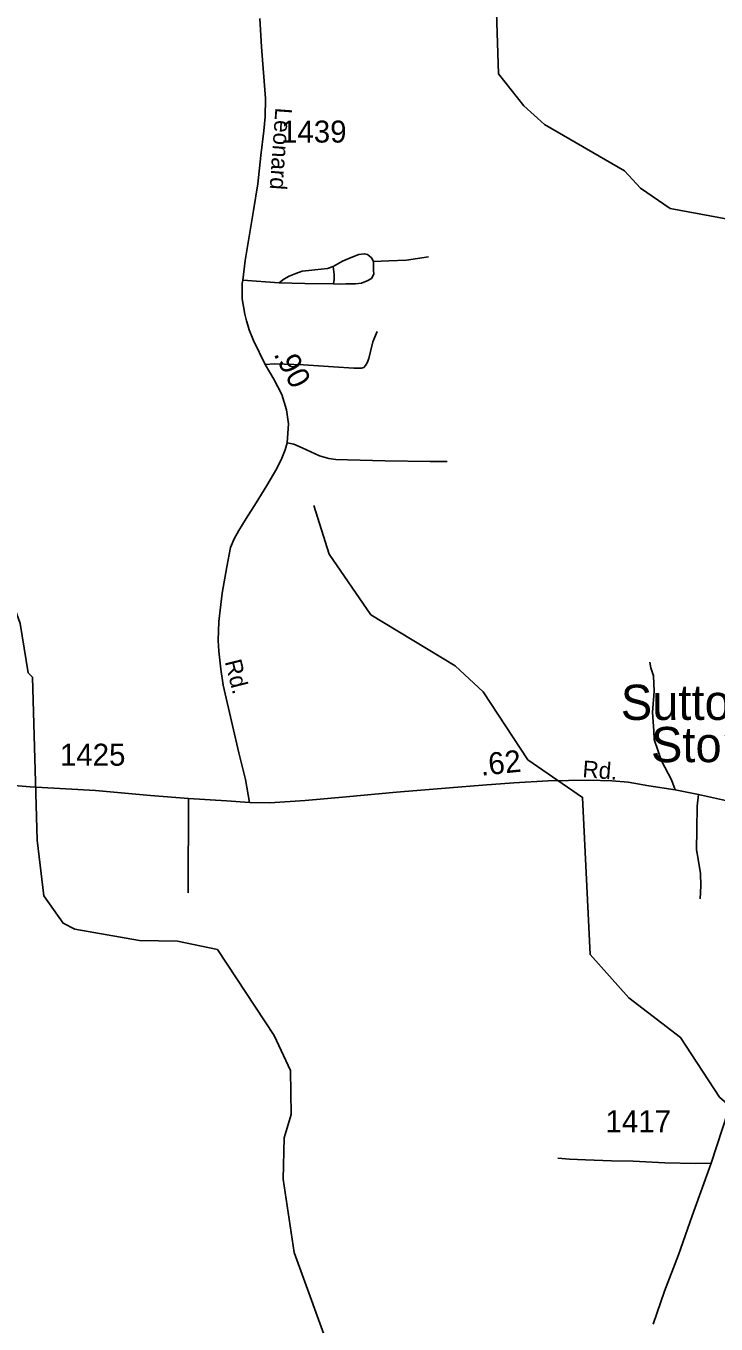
# Model space of a CAD drawing. Extents: x 2220236 to 2384410, y 720751 to 894131.
# Drawn here: x 2304658 to 2308575, y 834809 to 842180 of the extents above; entities that cross this region are included whole.
import ezdxf

# ---------------------------------------------------------------- set-up
doc = ezdxf.new("R2010")
doc.units = 0
doc.layers.add('Default', color=7, linetype='Continuous')

msp = doc.modelspace()

# ---------------------------------------------------------------- linework, layer by layer
at = {"layer": 'Default'}
for p, q in [((2305888.3, 840736.6), (2306094.8, 840721.5)), ((2305581.1, 837793.1), (2305578.8, 837257.6))]:
    msp.add_line(p, q, dxfattribs=at)
for points in [[(2305986.3, 842222.6), (2305995.2, 842061.1), (2306017.4, 841768.3), (2306015.6, 841663.6), (2306007.6, 841583.7), (2305991.7, 841443.5), (2305973.9, 841283.8), (2305949.1, 841131.2), (2305903, 840847.3), (2305888.3, 840736.6), (2305885.9, 840718.1), (2305885.2, 840630.7), (2305899.8, 840543.8), (2305910.1, 840504.7), (2305917.2, 840479.9), (2305926, 840453.3), (2305948.8, 840394.3), (2306015.9, 840258.1), (2306065.6, 840173.7), (2306110.8, 840086), (2306137.1, 839999.8), (2306148.8, 839919.5), (2306141.2, 839813.2), (2306129.1, 839771.8), (2306111.4, 839725.7), (2306083, 839667.1), (2306026.2, 839569.5), (2305964.2, 839471.9), (2305907.4, 839383.2), (2305866.6, 839314), (2305840, 839267.8), (2305818.7, 839218.1), (2305797.4, 839108.7), (2305772.6, 838957.9), (2305753.1, 838797.6), (2305749.6, 838689.3), (2305753.1, 838629), (2305764.9, 838527.1), (2305778, 838437.3), (2305831.2, 838206.6), (2305866.6, 838052.2), (2305903.9, 837901.4), (2305927.8, 837770.1)], [(2315151.5, 839877.9), (2315000.4, 839917.7), (2314477.5, 839745.3), (2313171.3, 839645.9), (2312490.3, 839447.4), (2312107.3, 839434.9), (2311956.3, 839507.5), (2311720.3, 839790), (2311227.4, 839891.2), (2310983.4, 840097.8), (2310907.3, 840265.4), (2310738.3, 840445.6), (2310478.3, 840602.3), (2310233.3, 840891), (2310091.2, 841003.3), (2309832.2, 841078), (2308816.1, 841049.5), (2308315.2, 841143.9), (2308147.2, 841258.5), (2308055.2, 841356.4), (2307602.2, 841620.1), (2307484.1, 841726.9), (2307341.2, 841908.1), (2307329.1, 842258.8)], [(2306630.1, 840841.9), (2306619.5, 840863.2), (2306607.1, 840873.9), (2306596.4, 840881), (2306578.7, 840886.3), (2306548.5, 840882.7), (2306504.2, 840865), (2306454.5, 840843.7), (2306401.3, 840813.5)], [(2306630.1, 840841.9), (2306718.8, 840845.5), (2306818.1, 840849), (2306942.2, 840868.5)], [(2306401.3, 840813.5), (2306369.4, 840802.9), (2306298.5, 840794), (2306263, 840790.5), (2306225.8, 840786.9), (2306190.3, 840774.5), (2306153, 840758.5), (2306121.1, 840742.5), (2306094.8, 840721.5)], [(2306401.3, 840813.5), (2306406.7, 840769.2), (2306408.4, 840739), (2306404, 840715.7)], [(2306404, 840715.7), (2306443.1, 840714.3), (2306474.4, 840715.1), (2306499.8, 840715.1), (2306529.2, 840715.7), (2306562.7, 840719.5), (2306594.6, 840731.9), (2306619.5, 840746.1), (2306631.9, 840770.9), (2306630.1, 840792.2), (2306630.1, 840822.4), (2306630.1, 840841.9)], [(2306094.8, 840721.5), (2306241.7, 840717.7), (2306404, 840715.7)], [(2306652.3, 840444.4), (2306627.5, 840385.8), (2306613.3, 840330.8), (2306604.4, 840291.8), (2306595.5, 840266.9), (2306584.9, 840251), (2306576, 840240.3), (2306563.6, 840236.8), (2306519.3, 840236.8), (2306404, 840243.9), (2306233.7, 840254.5), (2306070.6, 840261.6), (2306015.9, 840258.1)], [(2305519.1, 836982.7), (2305303.1, 836986.9), (2304936.1, 837050.7), (2304869.2, 837084.1), (2304759.1, 837240.4), (2304722.2, 837557.2), (2304695.1, 838481.7), (2304670.1, 838506.9), (2304625, 838787.3), (2304531.1, 839052.6), (2303938.1, 839957.1), (2303853, 840104.6)], [(2307049.5, 839706.2), (2306952.9, 839706.2), (2306697.5, 839709.7), (2306482.9, 839716.8), (2306417.3, 839718.6), (2306376.5, 839723.9), (2306325.1, 839738.1), (2306225.8, 839784.3), (2306177.9, 839805.5), (2306141.2, 839813.2)], [(2309591.3, 835616.7), (2309432.3, 835616.8), (2309173.4, 835671.8), (2308973.2, 835768.6), (2308594.3, 836097.8), (2308374.3, 836436.6), (2308080.2, 836660.9), (2307861.2, 836907.9), (2307818.1, 837798.8), (2307507.3, 838012.6), (2307254.2, 838399.3), (2307094.3, 838547), (2306616.1, 838836), (2306379.3, 839180.7), (2306293.1, 839456.2)], [(2308343.3, 837842.8), (2308322, 837899.6), (2308265.3, 838006.1), (2308247.5, 838061.1), (2308224.5, 838128.5), (2308222.7, 838176.4), (2308215.6, 838281.2), (2308224.5, 838401.8), (2308220.9, 838488.8), (2308205, 838534.9), (2308199.6, 838566.9)], [(2301495.9, 838290), (2301666.2, 838243.9), (2301832.9, 838199.5), (2302040.4, 838151.6), (2302324.2, 838085.9), (2302501.5, 838046.9), (2302641.6, 838020.3), (2302769.3, 837997.2), (2302955.6, 837970.6), (2303088.6, 837959.9), (2303149.8, 837952.8), (2303447.7, 837938.6), (2303871.6, 837915.6), (2304284.8, 837887.2), (2304428.5, 837880.1), (2304682.1, 837858.8), (2305052.6, 837837.5), (2305364.7, 837809.1), (2305581.1, 837793.1), (2305795.7, 837778.9), (2305927.8, 837770.1)], [(2305927.8, 837770.1), (2306043.1, 837768.3), (2306243.5, 837780.7), (2306474.9, 837802), (2306762.2, 837828.6), (2307062, 837853.5), (2307249.9, 837867.7), (2307428.2, 837881.9), (2307623.3, 837892.5), (2307853.8, 837897.8), (2307983.3, 837892.5), (2308077.3, 837885.4), (2308194.3, 837864.1), (2308343.3, 837842.8), (2308475.4, 837816.2), (2308679.4, 837770.1), (2308959.6, 837695.5), (2309157.3, 837640.5)], [(2308475.4, 837816.2), (2308468.3, 837748.8), (2308466.6, 837617.4), (2308464.8, 837502.1), (2308473.5, 837448.7), (2308486.9, 837367.2), (2308488.7, 837296.2), (2308485.2, 837223.5)], [(2309157.3, 837640.5), (2309137.8, 837560.7), (2309113, 837466.6), (2309075.7, 837321.1), (2309035, 837177.3), (2308925, 836852.6), (2308739.7, 836307.8), (2308547.2, 835722.1), (2308439.9, 835424), (2308361.9, 835202.2), (2308283, 834994.6), (2308219.2, 834808.2)], [(2306528.2, 833026.6), (2306502.3, 833169.9), (2306374.2, 833417.4), (2306305.3, 833624.6), (2306406.2, 834350.7), (2306394.3, 834626), (2306180.2, 835214.5), (2306117.2, 835632), (2306123.2, 835865.3), (2306163.2, 835998.2), (2306160.3, 836247.5), (2306067.2, 836447.1), (2305745.2, 836936.2), (2305519.1, 836982.7)], [(2308547.2, 835722.1), (2308460.3, 835720.4), (2308284.8, 835723.9), (2308105.6, 835732.8), (2307981.5, 835736.3), (2307834.3, 835741.7), (2307743, 835745.2), (2307677.4, 835750.5)]]:
    msp.add_lwpolyline(points, dxfattribs=at)

# ---------------------------------------------------------------- texts
for s, height, rotation, p in [('Leonard', 95, 265.94933, (2306074.5, 841717.7)), ('.90', 125, 297.89876, (2306061.6, 840316.4)), ('Rd.', 95, 284.10586, (2305786.1, 838570.2)), ('.62', 125, 5.91929, (2307243, 837921.8)), ('Rd.', 95, 355.31969, (2307814.6, 837914.9))]:
    msp.add_text(s, height=height, rotation=rotation, dxfattribs=at).set_placement(p)
for s, height, p in [('1439', 125, (2306106.1, 841517.4)), ('Suttons', 200, (2308034.6, 838239.2)), ('Store', 200, (2308205.9, 837999.2)), ('1425', 125, (2304850.9, 837979)), ('1417', 125, (2307948, 835897.7))]:
    msp.add_text(s, height=height, dxfattribs=at).set_placement(p)

doc.saveas('drawing.dxf')
